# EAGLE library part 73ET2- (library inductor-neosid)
FILTER triple helix bandpass with 2 tab, Type E
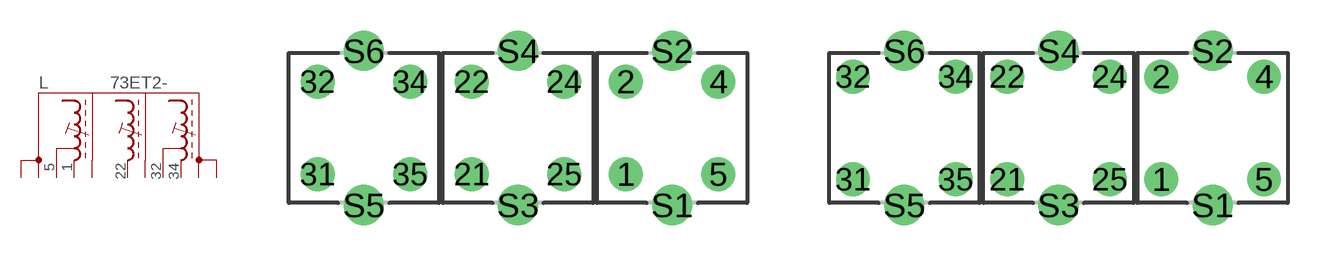
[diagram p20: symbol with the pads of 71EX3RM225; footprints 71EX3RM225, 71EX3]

Designator prefix L

## 73ET2-51223234-225 (OC_FARNELL: unknown; OC_NEWARK: unknown)  [71EX3RM225]
1  GND1  pas
5  IN  pas
22  GND2  pas
32  OUT1  pas
34  GND3  pas
S1  S1  pas
S2  S2  pas
S3  S3  pas
S4  S4  pas
S5  S5  pas
S6  S6  pas

## 73ET2-45223132 (OC_FARNELL: unknown; OC_NEWARK: unknown)  [71EX3RM225]
4  IN  pas
5  GND1  pas
22  GND2  pas
31  OUT1  pas
32  GND3  pas
S1  S1  pas
S2  S2  pas
S3  S3  pas
S4  S4  pas
S5  S5  pas
S6  S6  pas

## 73ET2-52243235 (OC_FARNELL: unknown; OC_NEWARK: unknown)  [71EX3]
2  GND1  pas
5  IN  pas
24  GND2  pas
32  OUT1  pas
34  GND3  pas
S1  S1  pas
S2  S2  pas
S3  S3  pas
S4  S4  pas
S5  S5  pas
S6  S6  pas

## 73ET2-51223234-250 (OC_FARNELL: unknown; OC_NEWARK: unknown)  [71EX3]
Pads as for 71EX3RM225

## 73ET2-54223231-250 (OC_FARNELL: unknown; OC_NEWARK: unknown)  [71EX3]
4  GND1  pas
5  IN  pas
22  GND2  pas
31  GND3  pas
32  OUT1  pas
S1  S1  pas
S2  S2  pas
S3  S3  pas
S4  S4  pas
S5  S5  pas
S6  S6  pas

## Footprint 71EX3RM225 (pad centres in mm)
TRIPLE RF COIL ASSEMBLY 1 winding, 4 pads, grid 2.25 mm
drill 1.1 round: 1 5.25,-2.25; 2 5.25,2.25; 4 9.75,2.25; 5 9.75,-2.25; 21 -2.25,-2.25; 22 -2.25,2.25; 24 2.25,2.25; 25 2.25,-2.25; 31 -9.75,-2.25; 32 -9.75,2.25; 34 -5.25,2.25; 35 -5.25,-2.25
drill 1.3 round: S1 7.5,-3.75; S2 7.5,3.75; S3 0,-3.75; S4 0,3.75; S5 -7.5,-3.75; S6 -7.5,3.75

## Footprint 71EX3 (pad centres in mm)
TRIPLE RF COIL ASSEMBLY 1 winding, 4 pads, grid 2.5 mm
drill 1.1 round: 1 5,-2.5; 2 5,2.5; 4 10,2.5; 5 10,-2.5; 21 -2.5,-2.5; 22 -2.5,2.5; 24 2.5,2.5; 25 2.5,-2.5; 31 -10,-2.5; 32 -10,2.5; 34 -5,2.5; 35 -5,-2.5
drill 1.3 round: S1 7.5,-3.75; S2 7.5,3.75; S3 0,-3.75; S4 0,3.75; S5 -7.5,-3.75; S6 -7.5,3.75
